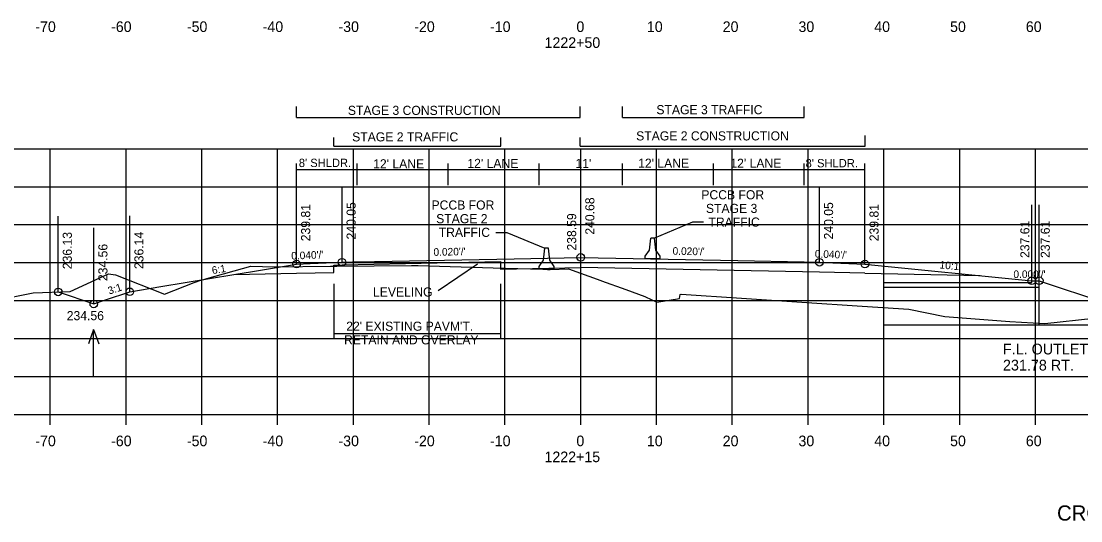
# Model space of a CAD drawing. Extents: x 1342547 to 1344156, y -1532351 to -1517216.
# Drawn here: x 1342629 to 1342768.9, y -1531705.2 to -1531639.3 of the extents above; entities that cross this region are included whole.
import ezdxf

# ---------------------------------------------------------------- set-up
doc = ezdxf.new("R2010")
doc.units = 0
for name, color, linetype in [('R_Alt Surface', 7, 'Continuous'), ('R_Axis', 7, 'Continuous'), ('R_Axis Annot', 7, 'Continuous'), ('R_Border Notes', 7, 'Continuous'), ('R_Draft', 7, 'Continuous'), ('R_Exist Surface', 7, 'Continuous'), ('R_Fin Surface', 7, 'Continuous'), ('R_Grid', 7, 'Continuous'), ('R_MOT', 7, 'Continuous'), ('R_No Plot', 7, 'Continuous'), ('R_Water', 7, 'Continuous'), ('R_Water Annot', 7, 'Continuous'), ('R_Xsect Elev', 7, 'Continuous'), ('R_Xsect Slope', 7, 'Continuous')]:
    doc.layers.add(name, color=color, linetype=linetype)

msp = doc.modelspace()

# ---------------------------------------------------------------- linework, layer by layer
at = {"layer": 'R_Alt Surface'}
for points in [[(1342670.29, -1531672.44), (1342670.3, -1531671.46), (1342671.37, -1531671.42), (1342692.29, -1531671)], [(1342692.29, -1531671), (1342692.3, -1531672), (1342702.87, -1531671.79)], [(1342740.37, -1531672.54), (1342734.37, -1531672.42), (1342702.87, -1531671.79)], [(1342657.09, -1531672.71), (1342665.37, -1531672.54)], [(1342665.37, -1531672.54), (1342670.29, -1531672.44)], [(1342740.37, -1531672.54), (1342755.56, -1531672.85)]]:
    msp.add_lwpolyline(points, dxfattribs=at)
at = {"layer": 'R_Axis'}
for p, q in [((1342562.87, -1531691.14), (1342842.87, -1531691.14)), ((1342632.87, -1531692.54), (1342632.87, -1531691.14)), ((1342642.87, -1531692.54), (1342642.87, -1531691.14)), ((1342652.87, -1531692.54), (1342652.87, -1531691.14)), ((1342662.87, -1531692.54), (1342662.87, -1531691.14)), ((1342672.87, -1531692.54), (1342672.87, -1531691.14)), ((1342682.87, -1531692.54), (1342682.87, -1531691.14)), ((1342692.87, -1531692.54), (1342692.87, -1531691.14)), ((1342702.87, -1531692.54), (1342702.87, -1531691.14)), ((1342712.87, -1531692.54), (1342712.87, -1531691.14)), ((1342722.87, -1531692.54), (1342722.87, -1531691.14)), ((1342732.87, -1531692.54), (1342732.87, -1531691.14)), ((1342742.87, -1531692.54), (1342742.87, -1531691.14)), ((1342752.87, -1531692.54), (1342752.87, -1531691.14)), ((1342762.87, -1531692.54), (1342762.87, -1531691.14))]:
    msp.add_line(p, q, dxfattribs=at)
at = {"layer": 'R_Draft'}
for p, q in [((1342665.37, -1531652), (1342665.37, -1531650.57)), ((1342702.78, -1531652), (1342702.78, -1531650.57)), ((1342708.37, -1531652), (1342708.37, -1531650.57)), ((1342732.37, -1531652), (1342732.37, -1531650.57)), ((1342665.37, -1531652), (1342702.78, -1531652)), ((1342708.37, -1531652), (1342732.37, -1531652)), ((1342670.3, -1531655.8), (1342670.3, -1531654.65)), ((1342692.31, -1531655.8), (1342692.31, -1531654.65)), ((1342702.78, -1531655.8), (1342702.78, -1531654.65)), ((1342740.38, -1531655.8), (1342740.38, -1531654.37)), ((1342670.3, -1531655.8), (1342692.31, -1531655.8)), ((1342702.78, -1531655.8), (1342740.38, -1531655.8)), ((1342670.29, -1531673.96), (1342670.29, -1531681.16)), ((1342692.3, -1531673.96), (1342692.3, -1531681.16)), ((1342670.29, -1531680.48), (1342692.3, -1531680.48))]:
    msp.add_line(p, q, dxfattribs=at)
for points in [[(1342717.62, -1531665.81), (1342712.61, -1531667.9)], [(1342719.06, -1531665.81), (1342717.62, -1531665.81)], [(1342691.67, -1531667.17), (1342693.11, -1531667.17)], [(1342693.11, -1531667.17), (1342698.11, -1531669.26)]]:
    msp.add_lwpolyline(points, dxfattribs=at)
at = {"layer": 'R_Exist Surface'}
msp.add_lwpolyline([(1342625.79, -1531676.08), (1342630.6, -1531675.14), (1342635.52, -1531674.95), (1342640.57, -1531672.62), (1342641.48, -1531672.77), (1342647.95, -1531675.3), (1342651.88, -1531673.75), (1342652.87, -1531673.39), (1342653.15, -1531673.36), (1342653.55, -1531673.22), (1342659.32, -1531671.59), (1342662.44, -1531671.68), (1342662.44, -1531671.68), (1342662.5, -1531671.68), (1342669.86, -1531671.63), (1342670.69, -1531671.62), (1342680.52, -1531671.52), (1342681.41, -1531671.54), (1342691.33, -1531671.82), (1342697.88, -1531672.02), (1342698.47, -1531672.04), (1342698.83, -1531672.04), (1342701.24, -1531671.97), (1342705.5, -1531673.49), (1342705.62, -1531673.53), (1342708.82, -1531674.69), (1342711.31, -1531675.59), (1342711.41, -1531675.63), (1342712.93, -1531676.37), (1342715.91, -1531675.86), (1342716.01, -1531675.34), (1342716.1, -1531675.32), (1342740, -1531676.89), (1342746.15, -1531677.26), (1342750.89, -1531678.24), (1342759.5, -1531678.9), (1342764.09, -1531679.18), (1342770.59, -1531678.48)], dxfattribs=at)
at = {"layer": 'R_Fin Surface'}
msp.add_lwpolyline([(1342633.92, -1531675.01), (1342638.62, -1531676.58), (1342640.17, -1531676.06), (1342643.37, -1531674.99), (1342647.45, -1531674.31), (1342657.09, -1531672.71), (1342659.56, -1531672.3), (1342665.37, -1531671.33), (1342667.15, -1531671.26), (1342671.37, -1531671.09), (1342672.77, -1531671.06), (1342673.37, -1531671.05), (1342694.08, -1531670.63), (1342702.87, -1531670.46), (1342723.58, -1531670.87), (1342732.37, -1531671.05), (1342733.77, -1531671.08), (1342734.37, -1531671.09), (1342736.15, -1531671.16), (1342740.37, -1531671.33), (1342762.37, -1531673.53), (1342763.37, -1531673.53), (1342780.87, -1531679.36), (1342797.29, -1531673.88)], dxfattribs=at)
at = {"layer": 'R_Grid'}
for p, q in [((1342562.87, -1531656.14), (1342842.87, -1531656.14)), ((1342632.87, -1531691.14), (1342632.87, -1531656.14)), ((1342642.87, -1531691.14), (1342642.87, -1531656.14)), ((1342652.87, -1531691.14), (1342652.87, -1531656.14)), ((1342662.87, -1531691.14), (1342662.87, -1531656.14)), ((1342672.87, -1531691.14), (1342672.87, -1531656.14)), ((1342682.87, -1531691.14), (1342682.87, -1531656.14)), ((1342692.87, -1531691.14), (1342692.87, -1531656.14)), ((1342702.87, -1531691.14), (1342702.87, -1531656.14)), ((1342712.87, -1531691.14), (1342712.87, -1531656.14)), ((1342722.87, -1531691.14), (1342722.87, -1531656.14)), ((1342732.87, -1531691.14), (1342732.87, -1531656.14)), ((1342742.87, -1531691.14), (1342742.87, -1531656.14)), ((1342752.87, -1531691.14), (1342752.87, -1531656.14)), ((1342762.87, -1531691.14), (1342762.87, -1531656.14)), ((1342562.87, -1531661.14), (1342842.87, -1531661.14)), ((1342562.87, -1531666.14), (1342842.87, -1531666.14)), ((1342562.87, -1531671.14), (1342842.87, -1531671.14)), ((1342562.87, -1531676.14), (1342842.87, -1531676.14)), ((1342562.87, -1531681.14), (1342842.87, -1531681.14)), ((1342562.87, -1531686.14), (1342842.87, -1531686.14)), ((1342562.87, -1531691.14), (1342842.87, -1531691.14))]:
    msp.add_line(p, q, dxfattribs=at)
at = {"layer": 'R_MOT'}
for p, q in [((1342711.95, -1531669.48), (1342712.11, -1531667.9)), ((1342712.36, -1531667.9), (1342712.11, -1531667.9)), ((1342712.61, -1531667.9), (1342712.36, -1531667.9)), ((1342712.78, -1531669.48), (1342712.61, -1531667.9)), ((1342697.95, -1531670.84), (1342698.11, -1531669.26)), ((1342698.36, -1531669.26), (1342698.11, -1531669.26)), ((1342698.61, -1531669.26), (1342698.36, -1531669.26)), ((1342698.78, -1531670.84), (1342698.61, -1531669.26)), ((1342711.36, -1531670.65), (1342711.37, -1531670.31)), ((1342713.37, -1531670.65), (1342711.36, -1531670.65)), ((1342711.37, -1531670.31), (1342711.95, -1531669.48)), ((1342713.37, -1531670.31), (1342712.78, -1531669.48)), ((1342713.37, -1531670.65), (1342713.37, -1531670.31)), ((1342697.37, -1531671.67), (1342697.95, -1531670.84)), ((1342697.37, -1531672.01), (1342697.37, -1531671.67)), ((1342699.37, -1531672.01), (1342697.37, -1531672.01)), ((1342699.37, -1531671.67), (1342698.78, -1531670.84)), ((1342699.37, -1531672.01), (1342699.37, -1531671.67))]:
    msp.add_line(p, q, dxfattribs=at)
at = {"layer": 'R_No Plot'}
for centre in [(1342665.37, -1531671.33), (1342665.37, -1531671.33), (1342671.37, -1531671.09), (1342671.37, -1531671.09), (1342702.87, -1531670.46), (1342702.87, -1531670.46), (1342734.37, -1531671.09), (1342734.37, -1531671.09), (1342740.37, -1531671.33), (1342740.37, -1531671.33), (1342762.37, -1531673.53), (1342762.37, -1531673.53), (1342763.37, -1531673.53), (1342763.37, -1531673.53), (1342633.92, -1531675.01), (1342633.92, -1531675.01), (1342643.37, -1531674.99), (1342643.37, -1531674.99), (1342638.62, -1531676.58), (1342638.62, -1531676.58)]:
    msp.add_circle(centre, 0.5, dxfattribs=at)
at = {"layer": 'R_Water'}
for p, q in [((1342763.37, -1531679.36), (1342763.37, -1531673.53)), ((1342742.87, -1531673.78), (1342762.37, -1531673.78)), ((1342742.87, -1531674.36), (1342762.37, -1531674.36)), ((1342638.6, -1531679.94), (1342637.9, -1531681.86)), ((1342638.6, -1531686.22), (1342638.6, -1531679.94)), ((1342638.6, -1531679.94), (1342639.3, -1531681.86))]:
    msp.add_line(p, q, dxfattribs=at)
for points in [[(1342762.37, -1531673.78), (1342762.37, -1531673.53), (1342763.37, -1531673.53)], [(1342762.37, -1531674.36), (1342763.37, -1531674.36)], [(1342742.87, -1531679.36), (1342780.87, -1531679.36)]]:
    msp.add_lwpolyline(points, dxfattribs=at)
at = {"layer": 'R_Xsect Elev'}
for p, q in [((1342665.37, -1531671.33), (1342665.37, -1531658.08)), ((1342673.37, -1531660.94), (1342673.37, -1531658.08)), ((1342685.37, -1531660.94), (1342685.37, -1531658.08)), ((1342697.37, -1531660.94), (1342697.37, -1531658.08)), ((1342708.37, -1531660.94), (1342708.37, -1531658.08)), ((1342720.37, -1531660.94), (1342720.37, -1531658.08)), ((1342732.37, -1531660.94), (1342732.37, -1531658.08)), ((1342740.37, -1531671.33), (1342740.37, -1531658.08)), ((1342740.37, -1531658.93), (1342665.37, -1531658.93)), ((1342702.87, -1531670.46), (1342702.87, -1531660.46)), ((1342665.37, -1531671.33), (1342665.37, -1531661.33)), ((1342665.37, -1531671.33), (1342665.37, -1531661.33)), ((1342671.37, -1531671.09), (1342671.37, -1531661.09)), ((1342734.37, -1531671.09), (1342734.37, -1531661.09)), ((1342740.37, -1531671.33), (1342740.37, -1531661.33)), ((1342740.37, -1531671.33), (1342740.37, -1531661.33)), ((1342702.87, -1531672.55), (1342702.87, -1531662.55)), ((1342762.37, -1531673.53), (1342762.37, -1531663.53)), ((1342763.37, -1531673.53), (1342763.37, -1531663.53)), ((1342633.92, -1531675.01), (1342633.92, -1531665.01)), ((1342643.37, -1531674.99), (1342643.37, -1531664.99)), ((1342638.62, -1531676.58), (1342638.62, -1531666.58)), ((1342689.26, -1531671.36), (1342684.06, -1531674.85))]:
    msp.add_line(p, q, dxfattribs=at)

# ---------------------------------------------------------------- texts
at = {"layer": 'R_Axis Annot'}
for s, p in [('-70', (1342630.9, -1531640.75)), ('-60', (1342640.9, -1531640.75)), ('-50', (1342650.9, -1531640.75)), ('-40', (1342660.9, -1531640.75)), ('-30', (1342670.9, -1531640.75)), ('-20', (1342680.9, -1531640.75)), ('-10', (1342690.9, -1531640.75)), ('0', (1342702.3, -1531640.75)), ('10', (1342711.6, -1531640.75)), ('20', (1342721.6, -1531640.75)), ('30', (1342731.6, -1531640.75)), ('40', (1342741.6, -1531640.75)), ('50', (1342751.6, -1531640.75)), ('60', (1342761.6, -1531640.75)), ('1222+50', (1342698.1, -1531642.85)), ('-70', (1342630.9, -1531695.34)), ('-60', (1342640.9, -1531695.34)), ('-50', (1342650.9, -1531695.34)), ('-40', (1342660.9, -1531695.34)), ('-30', (1342670.9, -1531695.34)), ('-20', (1342680.9, -1531695.34)), ('-10', (1342690.9, -1531695.34)), ('0', (1342702.3, -1531695.34)), ('10', (1342711.6, -1531695.34)), ('20', (1342721.6, -1531695.34)), ('30', (1342731.6, -1531695.34)), ('40', (1342741.6, -1531695.34)), ('50', (1342751.6, -1531695.34)), ('60', (1342761.6, -1531695.34)), ('1222+15', (1342698.09, -1531697.44))]:
    msp.add_text(s, height=1.4, dxfattribs=at).set_placement(p)
at = {"layer": 'R_Border Notes'}
for s, height, p in [('F.L. OUTLET', 1.4147, (1342758.58, -1531683.24)), ('F.L. OUTLET', 1.4147, (1342758.58, -1531683.24)), ('231.78 RT.', 1.415, (1342758.58, -1531685.36)), ('231.78 RT.', 1.415, (1342758.58, -1531685.36))]:
    msp.add_text(s, height=height, dxfattribs=at).set_placement(p)
at = {"layer": 'R_Draft'}
for s, height, p in [('STAGE 3 CONSTRUCTION', 1.2, (1342672.14, -1531651.68)), ('STAGE 3 TRAFFIC', 1.2, (1342712.85, -1531651.59)), ('STAGE 2 TRAFFIC', 1.2, (1342672.71, -1531655.17)), ('STAGE 2 CONSTRUCTION', 1.2, (1342710.18, -1531655.04)), ('PCCB FOR', 1.2, (1342718.78, -1531662.8)), ('PCCB FOR', 1.2, (1342683.18, -1531664.15)), ('STAGE 3', 1.2, (1342719.39, -1531664.6)), ('STAGE 2', 1.2, (1342683.79, -1531665.95)), ('TRAFFIC', 1.2, (1342719.72, -1531666.4)), ('TRAFFIC', 1.2, (1342684.13, -1531667.75)), ("22' EXISTING PAVM'T.", 1.2, (1342671.93, -1531680.12)), ('RETAIN AND OVERLAY', 1.2, (1342671.64, -1531681.92)), ('CROSS SECTION STA.1222+15 TO STA. 1222+59', 2, (1342765.72, -1531705.14))]:
    msp.add_text(s, height=height, dxfattribs=at).set_placement(p)
at = {"layer": 'R_Water Annot'}
msp.add_text('234.56', height=1.2, dxfattribs=at).set_placement((1342635.05, -1531678.73))
msp.add_text('234.56', height=1.2, dxfattribs=at).set_placement((1342635.05, -1531678.73))
at = {"layer": 'R_Xsect Elev'}
for s, height, p in [("8' SHLDR.", 1.1, (1342665.67, -1531658.55)), ("12' LANE", 1.2, (1342675.48, -1531658.72)), ("12' LANE", 1.2, (1342687.91, -1531658.67)), ("11'", 1.2, (1342702.18, -1531658.67)), ("12' LANE", 1.2, (1342710.44, -1531658.64)), ("12' LANE", 1.2, (1342722.61, -1531658.65)), ("8' SHLDR.", 1.1, (1342732.54, -1531658.59)), ('LEVELING', 1.2, (1342675.46, -1531675.61))]:
    msp.add_text(s, height=height, dxfattribs=at).set_placement(p)
for s, p in [('239.81', (1342667.17, -1531668.33)), ('240.05', (1342673.17, -1531668.09)), ('240.68', (1342704.67, -1531667.46)), ('240.05', (1342736.17, -1531668.09)), ('239.81', (1342742.17, -1531668.33)), ('238.59', (1342702.27, -1531669.55)), ('237.61', (1342762.07, -1531670.53)), ('237.61', (1342764.76, -1531670.53)), ('236.13', (1342635.72, -1531672.01)), ('236.14', (1342645.17, -1531671.99)), ('234.56', (1342640.42, -1531673.58))]:
    msp.add_text(s, height=1.2, rotation=90, dxfattribs=at).set_placement(p)
at = {"layer": 'R_Xsect Slope'}
for s, rotation, p in [("0.020'/'", 1.1458, (1342683.45, -1531670.25)), ("0.020'/'", 358.8542, (1342714.98, -1531670.1)), ("0.040'/'", 2.2906, (1342664.69, -1531670.75)), ("0.040'/'", 357.7094, (1342733.74, -1531670.46)), ('6:1', 9.4623, (1342654.28, -1531672.67)), ('10:1', 354.6341, (1342750.18, -1531671.9)), ("0.000'/'", 359.9313, (1342759.96, -1531673.17)), ('3:1', 18.4349, (1342640.66, -1531675.37))]:
    msp.add_text(s, height=1, rotation=rotation, dxfattribs=at).set_placement(p)

doc.saveas('drawing.dxf')
